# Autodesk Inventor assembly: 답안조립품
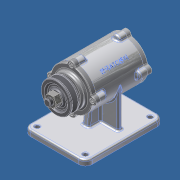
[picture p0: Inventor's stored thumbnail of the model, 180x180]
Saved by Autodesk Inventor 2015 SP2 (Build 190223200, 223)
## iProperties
Created: 2015-12
Part Number: 답안조립품
Document SubType Name: Assembly
Designer: AMC
Author: AMC
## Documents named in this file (11)
- C:\Users\AMC\Desktop\451207V1019\답안조립품.iam
- C:\Users\AMC\Desktop\451207V1019\본체.ipt
- C:\Users\AMC\Desktop\451207V1019\V-벨트풀리.ipt
- C:\Users\AMC\Desktop\451207V1019\베어링 6204.ipt
- C:\Users\AMC\Desktop\451207V1019\오일실.ipt
- C:\Users\AMC\Desktop\451207V1019\커버2.ipt
- C:\Users\AMC\Desktop\451207V1019\커버.ipt
- C:\Users\AMC\Desktop\451207V1019\키(4 x 4 x 12).ipt
- C:\Users\AMC\Desktop\451207V1019\축.ipt
- C:\Users\AMC\Desktop\451207V1019\너트 M12x1.25.ipt
- C:\Users\AMC\Desktop\451207V1019\볼트 M4 x 12.ipt
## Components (6 placed, 5 different names)
1. V-벨트풀리:1 — 각도:2
2. KS B 2023 6204 - 20 x 47 x 14:1
3. KS B 2023 6204 - 20 x 47 x 14:2
4. KS B 2804 D D - 20 32 8:1
5. KS B 1311 (I) 4 x 4 x 12:1 — 각도:1, 각도:2
6. KS B 1012 클래스 1 일반 - 미터 M12x1.25:1 — 각도:3
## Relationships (3: Angle 3)
- 각도:1 [Angle]: KS B 1311 (I) 4 x 4 x 12:1
- 각도:2 [Angle]: V-벨트풀리:1 ↔ KS B 1311 (I) 4 x 4 x 12:1
- 각도:3 [Angle]: KS B 1012 클래스 1 일반 - 미터 M12x1.25:1
